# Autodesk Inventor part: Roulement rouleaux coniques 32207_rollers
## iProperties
Created: 2000-12
Part Number: Roulement rouleaux coniques 32207_rollers
Material: Par défaut
Document SubType Name: Modélisation
Designer: Administrateur
Control State: 0
Master: False
Checked Out: False
Shininess: 20.0
Length Units: 11269
Angle Units: 11279
Time Units: 11290
Mass Units: 11283
Length Display Precision: 3
Angle Display Precision: 2
Density: 0.0
Volumn: 0.0
Area: 0.0
PropertySet Name: Model Information
Author: Administrateur
